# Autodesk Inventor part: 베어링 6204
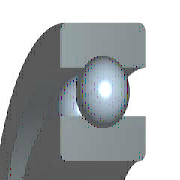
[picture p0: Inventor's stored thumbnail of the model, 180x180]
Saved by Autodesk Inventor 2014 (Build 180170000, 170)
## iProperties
IsCustomPart: 0
Manager: KYOUNG IL JANG
Company: 한국ATC센터
Created: 2009-02
Part Number: 베어링 6204
Material: Steel, Mild
Description: 깊은 그루브 볼 베어링
Document SubType Name: Modeling
Standard: KS B 2023
Standards Organization: KS
Language: ko-KR
Size Designation: 6204 - 20 x 47 x 14
Categories: <MemberInstance><Categories><Category DisplayName="샤프트 부품" InternalName="7f7aeb1f-a693-4053-b835-cee3144e0d98" Mnemonic="SHFT"><Category DisplayName="베어링" Inter
Density: 1 g/cm^3
Checked By: KYOUNG IL JANG
Vendor: CBT Solutions
Designer: KYOUNG IL JANG
Appearance: _시험-파란색 크롬
Author: KYOUNG IL JANG
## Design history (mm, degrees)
sketch "스케치" dims "d0" = 7.02 (= -0.26 x WD + 0.26 x BD)
  geometry: L1 (3.49, 16.75)-(10.51, 16.75); L2 (7, 16.75)-(7, 13.24); L3 (7, 16.75)-(7, 20.26); L4 (4.392, 14.401)-(0, 14.401); L5 (0, 10)-(14, 10); L6 (4.392, 19.099)-(0, 19.099); L7 (0, 23.5)-(14, 23.5); L8 (14, 10)-(14, 14.401); L9 (9.608, 14.401)-(14, 14.401); L10 (9.608, 19.099)-(14, 19.099); L11 (14, 23.5)-(14, 19.099); L12 (-1.4, 0)-(8.4, 0) reference; L13 (0, -0.3)-(0, 5.3) reference
  constraints: 22 end point, 4 point on line, 2 collinear, 2 perpendicular, 2 symmetric about line, 1 midpoint, 1 parallel, 14 other
  dimensions: "d9" = 20 diameter of L5 L12 (= WD); "d11" = 47 diameter of L7 L12 (= BD); "d12" = 14 distance between parallel lines of L8 L13 (= KB); "d13" = 28.802 diameter of L9 L12 (= 0.326 x BD + 0.674 x WD)
revolve "본체" stored, may be unused: angle "d6" = 90 deg
revolve "볼" stored, may be unused: angle "d7" = 90 deg
pattern_circular "IDS_ARRAYBALL[SIMPL:T]" dims angle "d3" = 360 deg
body "Solid1"
fillet "모깎기1" dims "d1" = 1 (= KRS)
other parameters: "WD" = 20 [user parameter; used in 5 equation terms], "BD" = 47 [user parameter; used in 5 equation terms], "KB" = 14 [user parameter; used in 1 equation term], "KRS" = 1 [user parameter; used in 1 equation term], "d4" = 0, "d5" = 0, "d8" = 0, "d14" = 0, "d15" = 0, "BBA" = 0 [user parameter], "BC0" = 6550000 [user parameter], "BC" = 1.27e+07 [user parameter], "BR" = 23.5 (= 0.5 x BD) [user parameter]
